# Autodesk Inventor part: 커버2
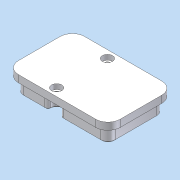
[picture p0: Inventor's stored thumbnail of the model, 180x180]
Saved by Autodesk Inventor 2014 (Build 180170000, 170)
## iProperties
Company: 한국ATC센터
Created: 2015-04
Part Number: 커버2
Document SubType Name: Modeling
Designer: KYOUNG IL JANG
Density: 1 g/cm^3
Material: 일반
Mass: 82.2849 g
Surface Area: 213.51 cm^2
Volume: 82.2849 cm^3
Appearance: 매끄러움 - 흰색
Author: KYOUNG IL JANG
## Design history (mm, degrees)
node "작업 평면1"
sketch "스케치1"
  geometry: L1 (-16.986, 27.5)-(-38, 27.5) reference; L2 (-45, 20.5)-(-45, -20.5) reference; L3 (-38, -27.5)-(-16.986, -27.5) reference; L4 (0.986, -27.5)-(38, -27.5) reference; L5 (45, -20.5)-(45, 20.5) reference; L6 (38, 27.5)-(0.986, 27.5) reference; C1 r 25 at (15, 0); A1 r 3 centre (-16.986, 24.5) between (-13.991, 24.667) and (-16.986, 27.5) reference; A2 r 7 centre (-38, 20.5) between (-38, 27.5) and (-45, 20.5) reference; A3 r 7 centre (-38, -20.5) between (-45, -20.5) and (-38, -27.5) reference; A4 r 3 centre (-16.986, -24.5) between (-16.986, -27.5) and (-13.991, -24.667) reference; A5 r 6 centre (-8, -25) between (-2.009, -24.667) and (-13.991, -24.667) reference; A6 r 3 centre (0.986, -24.5) between (-2.009, -24.667) and (0.986, -27.5) reference; A7 r 7 centre (38, -20.5) between (38, -27.5) and (45, -20.5) reference; A8 r 7 centre (38, 20.5) between (45, 20.5) and (38, 27.5) reference; A9 r 3 centre (0.986, 24.5) between (0.986, 27.5) and (-2.009, 24.667) reference; A10 r 6 centre (-8, 25) between (-13.991, 24.667) and (-2.009, 24.667) reference; 1 further point
  constraints: 20 point on circle, 12 end point, 11 centre point, 4 horizontal, 2 vertical, 36 other
extrude "돌출1" new body sketch "스케치1" distance "d0" = 14; taper "d1" = 0 deg
sketch "스케치2"
  geometry: L1 (38, -32.5)-(-38, -32.5) reference; L2 (50, 20.5)-(50, -20.5) reference; L3 (-38, 32.5)-(38, 32.5) reference; L4 (-50, -20.5)-(-50, 20.5) reference; A1 r 12 centre (38, -20.5) between (38, -32.5) and (50, -20.5) reference; A2 r 12 centre (38, 20.5) between (50, 20.5) and (38, 32.5) reference; A3 r 12 centre (-38, 20.5) between (-38, 32.5) and (-50, 20.5) reference; A4 r 12 centre (-38, -20.5) between (-50, -20.5) and (-38, -32.5) reference; 1 further point
extrude "돌출2" join sketch "스케치2" distance "d2" = 7; taper "d3" = 0 deg
sketch "스케치3"
  geometry: C1 r 2.458 at (-8, 25) reference; C2 r 2.458 at (-8, -25) reference; 1 further point
hole "구멍1" sketch "스케치3" at (-8, -25), (-8, 25) diameter "d4" = 6; stored, may be unused: countersink angle "d8" = 90 deg, drill point angle "d10" = 118 deg; dims "d5" = 6, "d6" = 10, "d7" = 5, "d9" = 8
fillet "모깎기1" dims "d11" = 0.3
chamfer "모따기1" distance "d12" = 1; stored, may be unused: second distance "d13" = 2, angle "d14" = 45 deg
node "솔리드1"
node "참조2"
node "참조3"
node "참조4"
node "참조5"
node "참조6"
node "참조7"
node "참조8"
node "참조9"
node "참조10"
node "참조11"
